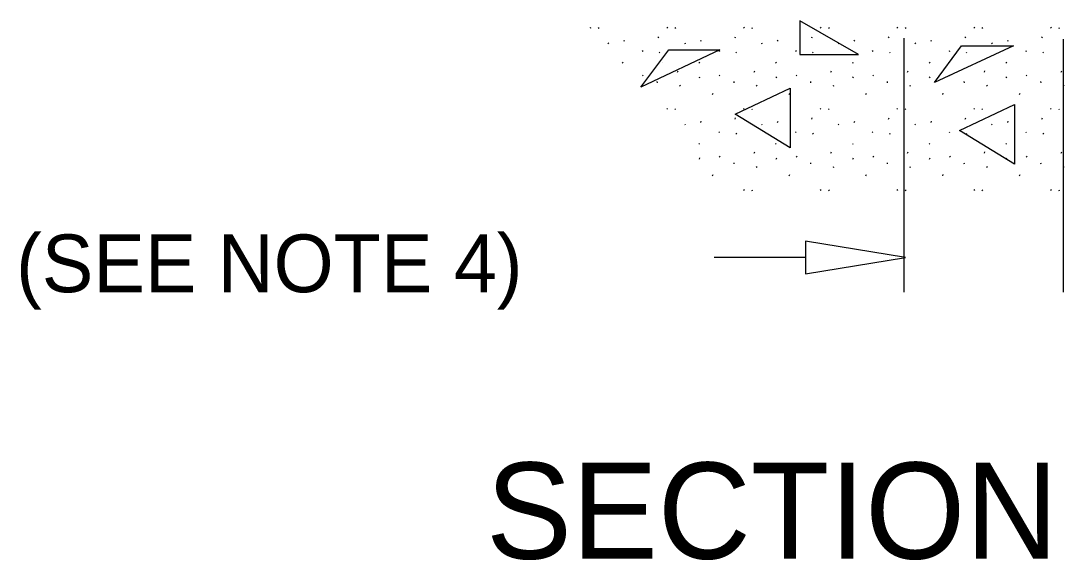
# Model space of a CAD drawing. Extents: x -1550.42 to -1543.2, y 2481.09 to 2491.
# Drawn here: x -1549.538 to -1548.454, y 2486.013 to 2486.573 of the extents above; entities that cross this region are included whole.
import ezdxf

# ---------------------------------------------------------------- set-up
doc = ezdxf.new("R2010")
doc.units = 0
for name, color, linetype in [('DETL-DIMS', 7, 'Continuous'), ('DETL-NOTE', 7, 'Continuous'), ('DETL-PATT', 7, 'Continuous'), ('DETL-TITL', 7, 'Continuous')]:
    doc.layers.add(name, color=color, linetype=linetype)

msp = doc.modelspace()

# ---------------------------------------------------------------- linework, layer by layer
at = {"layer": 'DETL-DIMS'}
for p, q in [((-1548.621, 2486.555), (-1548.621, 2486.291)), ((-1548.455, 2486.291), (-1548.455, 2486.554)), ((-1548.723, 2486.327), (-1548.818, 2486.327))]:
    msp.add_line(p, q, dxfattribs=at)
msp.add_lwpolyline([(-1548.723, 2486.344), (-1548.723, 2486.31), (-1548.619, 2486.327)], close=True, dxfattribs=at)
at = {"layer": 'DETL-PATT'}
for p, q in [((-1548.9468, 2486.5663), (-1548.9462, 2486.5654)), ((-1548.8671, 2486.5663), (-1548.8665, 2486.5654)), ((-1548.7874, 2486.5663), (-1548.7868, 2486.5654)), ((-1548.668, 2486.538), (-1548.729, 2486.573)), ((-1548.729, 2486.573), (-1548.729, 2486.538)), ((-1548.7077, 2486.5663), (-1548.7071, 2486.5654)), ((-1548.628, 2486.5663), (-1548.6274, 2486.5654)), ((-1548.5482, 2486.5663), (-1548.5476, 2486.5654)), ((-1548.4685, 2486.5663), (-1548.4679, 2486.5654)), ((-1548.9383, 2486.566), (-1548.9377, 2486.5651)), ((-1548.876, 2486.5552), (-1548.8754, 2486.5565)), ((-1548.8586, 2486.566), (-1548.858, 2486.5651)), ((-1548.7962, 2486.5552), (-1548.7956, 2486.5565)), ((-1548.7789, 2486.566), (-1548.7783, 2486.5651)), ((-1548.7165, 2486.5552), (-1548.7159, 2486.5565)), ((-1548.6991, 2486.566), (-1548.6985, 2486.5651)), ((-1548.6368, 2486.5552), (-1548.6362, 2486.5565)), ((-1548.6194, 2486.566), (-1548.6188, 2486.5651)), ((-1548.5571, 2486.5552), (-1548.5565, 2486.5565)), ((-1548.5397, 2486.566), (-1548.5391, 2486.5651)), ((-1548.4774, 2486.5552), (-1548.4768, 2486.5565)), ((-1548.46, 2486.566), (-1548.4594, 2486.5651)), ((-1548.9282, 2486.55), (-1548.9276, 2486.5491)), ((-1548.9115, 2486.5518), (-1548.9109, 2486.5531)), ((-1548.8485, 2486.55), (-1548.8479, 2486.5491)), ((-1548.8318, 2486.5518), (-1548.8312, 2486.5531)), ((-1548.7688, 2486.55), (-1548.7682, 2486.5491)), ((-1548.752, 2486.5518), (-1548.7514, 2486.5531)), ((-1548.6891, 2486.55), (-1548.6885, 2486.5491)), ((-1548.6723, 2486.5518), (-1548.6717, 2486.5531)), ((-1548.6094, 2486.55), (-1548.6088, 2486.5491)), ((-1548.5926, 2486.5518), (-1548.592, 2486.5531)), ((-1548.589, 2486.509), (-1548.561, 2486.547)), ((-1548.507, 2486.547), (-1548.589, 2486.509)), ((-1548.561, 2486.547), (-1548.507, 2486.547)), ((-1548.5297, 2486.55), (-1548.5291, 2486.5491)), ((-1548.5129, 2486.5518), (-1548.5123, 2486.5531)), ((-1548.894, 2486.504), (-1548.865, 2486.543)), ((-1548.812, 2486.543), (-1548.894, 2486.504)), ((-1548.8927, 2486.5422), (-1548.8921, 2486.5413)), ((-1548.875, 2486.5405), (-1548.8744, 2486.5396)), ((-1548.865, 2486.543), (-1548.812, 2486.543)), ((-1548.813, 2486.5422), (-1548.8124, 2486.5413)), ((-1548.7953, 2486.5405), (-1548.7947, 2486.5396)), ((-1548.7333, 2486.5422), (-1548.7327, 2486.5413)), ((-1548.729, 2486.538), (-1548.668, 2486.538)), ((-1548.7156, 2486.5405), (-1548.715, 2486.5396)), ((-1548.6536, 2486.5422), (-1548.653, 2486.5413)), ((-1548.6359, 2486.5405), (-1548.6353, 2486.5396)), ((-1548.5739, 2486.5422), (-1548.5733, 2486.5413)), ((-1548.5562, 2486.5405), (-1548.5556, 2486.5396)), ((-1548.4942, 2486.5422), (-1548.4936, 2486.5413)), ((-1548.4764, 2486.5405), (-1548.4758, 2486.5396)), ((-1548.9135, 2486.5299), (-1548.9129, 2486.529)), ((-1548.872, 2486.53), (-1548.872, 2486.53)), ((-1548.8337, 2486.5299), (-1548.8331, 2486.529)), ((-1548.754, 2486.5299), (-1548.7534, 2486.529)), ((-1548.6743, 2486.5299), (-1548.6737, 2486.529)), ((-1548.5946, 2486.5299), (-1548.594, 2486.529)), ((-1548.5149, 2486.5299), (-1548.5143, 2486.529)), ((-1548.8922, 2486.5166), (-1548.8916, 2486.5157)), ((-1548.856, 2486.5198), (-1548.8554, 2486.5212)), ((-1548.8332, 2486.5137), (-1548.8326, 2486.515)), ((-1548.8125, 2486.5166), (-1548.8119, 2486.5157)), ((-1548.7763, 2486.5198), (-1548.7757, 2486.5212)), ((-1548.7535, 2486.5137), (-1548.7529, 2486.515)), ((-1548.7327, 2486.5166), (-1548.7321, 2486.5157)), ((-1548.6966, 2486.5198), (-1548.696, 2486.5212)), ((-1548.6738, 2486.5137), (-1548.6732, 2486.515)), ((-1548.653, 2486.5166), (-1548.6524, 2486.5157)), ((-1548.6169, 2486.5198), (-1548.6163, 2486.5212)), ((-1548.5941, 2486.5137), (-1548.5935, 2486.515)), ((-1548.5733, 2486.5166), (-1548.5727, 2486.5157)), ((-1548.5372, 2486.5198), (-1548.5366, 2486.5212)), ((-1548.5144, 2486.5137), (-1548.5138, 2486.515)), ((-1548.4936, 2486.5166), (-1548.493, 2486.5157)), ((-1548.4574, 2486.5198), (-1548.4568, 2486.5212)), ((-1548.8773, 2486.5099), (-1548.8772, 2486.5086)), ((-1548.8538, 2486.506), (-1548.8532, 2486.5051)), ((-1548.7976, 2486.5099), (-1548.7975, 2486.5086)), ((-1548.796, 2486.476), (-1548.739, 2486.503)), ((-1548.7741, 2486.506), (-1548.7735, 2486.5051)), ((-1548.739, 2486.503), (-1548.739, 2486.441)), ((-1548.7179, 2486.5099), (-1548.7178, 2486.5086)), ((-1548.6944, 2486.506), (-1548.6938, 2486.5051)), ((-1548.6382, 2486.5099), (-1548.638, 2486.5086)), ((-1548.6147, 2486.506), (-1548.6141, 2486.5051)), ((-1548.5585, 2486.5099), (-1548.5583, 2486.5086)), ((-1548.535, 2486.506), (-1548.5344, 2486.5051)), ((-1548.4788, 2486.5099), (-1548.4786, 2486.5086)), ((-1548.4553, 2486.506), (-1548.4547, 2486.5051)), ((-1548.8196, 2486.4963), (-1548.819, 2486.4977)), ((-1548.7399, 2486.4963), (-1548.7393, 2486.4977)), ((-1548.6602, 2486.4963), (-1548.6596, 2486.4977)), ((-1548.5805, 2486.4963), (-1548.5799, 2486.4977)), ((-1548.5007, 2486.4963), (-1548.5001, 2486.4977)), ((-1548.8671, 2486.482), (-1548.8665, 2486.4811)), ((-1548.8586, 2486.4817), (-1548.858, 2486.4808)), ((-1548.7874, 2486.482), (-1548.7868, 2486.4811)), ((-1548.7789, 2486.4817), (-1548.7783, 2486.4808)), ((-1548.7077, 2486.482), (-1548.7071, 2486.4811)), ((-1548.6991, 2486.4817), (-1548.6985, 2486.4808)), ((-1548.628, 2486.482), (-1548.6274, 2486.4811)), ((-1548.6194, 2486.4817), (-1548.6188, 2486.4808)), ((-1548.563, 2486.459), (-1548.506, 2486.486)), ((-1548.5482, 2486.482), (-1548.5476, 2486.4811)), ((-1548.5397, 2486.4817), (-1548.5391, 2486.4808)), ((-1548.506, 2486.486), (-1548.506, 2486.424)), ((-1548.4685, 2486.482), (-1548.4679, 2486.4811)), ((-1548.46, 2486.4817), (-1548.4594, 2486.4808)), ((-1548.8318, 2486.4674), (-1548.8312, 2486.4688)), ((-1548.7962, 2486.4709), (-1548.7956, 2486.4722)), ((-1548.739, 2486.441), (-1548.796, 2486.476)), ((-1548.752, 2486.4674), (-1548.7514, 2486.4688)), ((-1548.7165, 2486.4709), (-1548.7159, 2486.4722)), ((-1548.6723, 2486.4674), (-1548.6717, 2486.4688)), ((-1548.6368, 2486.4709), (-1548.6362, 2486.4722)), ((-1548.5926, 2486.4674), (-1548.592, 2486.4688)), ((-1548.5571, 2486.4709), (-1548.5565, 2486.4722)), ((-1548.5129, 2486.4674), (-1548.5123, 2486.4688)), ((-1548.4774, 2486.4709), (-1548.4768, 2486.4722)), ((-1548.8485, 2486.4657), (-1548.8479, 2486.4648)), ((-1548.813, 2486.4578), (-1548.8124, 2486.4569)), ((-1548.7688, 2486.4657), (-1548.7682, 2486.4648)), ((-1548.7333, 2486.4578), (-1548.7327, 2486.4569)), ((-1548.6891, 2486.4657), (-1548.6885, 2486.4648)), ((-1548.6536, 2486.4578), (-1548.653, 2486.4569)), ((-1548.6094, 2486.4657), (-1548.6088, 2486.4648)), ((-1548.5739, 2486.4578), (-1548.5733, 2486.4569)), ((-1548.506, 2486.424), (-1548.563, 2486.459)), ((-1548.5297, 2486.4657), (-1548.5291, 2486.4648)), ((-1548.4942, 2486.4578), (-1548.4936, 2486.4569)), ((-1548.7953, 2486.4562), (-1548.7947, 2486.4553)), ((-1548.7156, 2486.4562), (-1548.715, 2486.4553)), ((-1548.6359, 2486.4562), (-1548.6353, 2486.4553)), ((-1548.5562, 2486.4562), (-1548.5556, 2486.4553)), ((-1548.4764, 2486.4562), (-1548.4758, 2486.4553)), ((-1548.8337, 2486.4456), (-1548.8331, 2486.4447)), ((-1548.7763, 2486.4355), (-1548.7757, 2486.4369)), ((-1548.754, 2486.4456), (-1548.7534, 2486.4447)), ((-1548.6966, 2486.4355), (-1548.696, 2486.4369)), ((-1548.6743, 2486.4456), (-1548.6737, 2486.4447)), ((-1548.6169, 2486.4355), (-1548.6163, 2486.4369)), ((-1548.5946, 2486.4456), (-1548.594, 2486.4447)), ((-1548.5372, 2486.4355), (-1548.5366, 2486.4369)), ((-1548.5149, 2486.4456), (-1548.5143, 2486.4447)), ((-1548.4574, 2486.4355), (-1548.4568, 2486.4369)), ((-1548.8332, 2486.4294), (-1548.8326, 2486.4307)), ((-1548.8125, 2486.4323), (-1548.8119, 2486.4314)), ((-1548.7976, 2486.4256), (-1548.7975, 2486.4243)), ((-1548.7535, 2486.4294), (-1548.7529, 2486.4307)), ((-1548.7327, 2486.4323), (-1548.7321, 2486.4314)), ((-1548.7179, 2486.4256), (-1548.7178, 2486.4243)), ((-1548.6738, 2486.4294), (-1548.6732, 2486.4307)), ((-1548.653, 2486.4323), (-1548.6524, 2486.4314)), ((-1548.6382, 2486.4256), (-1548.638, 2486.4243)), ((-1548.5941, 2486.4294), (-1548.5935, 2486.4307)), ((-1548.5733, 2486.4323), (-1548.5727, 2486.4314)), ((-1548.5585, 2486.4256), (-1548.5583, 2486.4243)), ((-1548.5144, 2486.4294), (-1548.5138, 2486.4307)), ((-1548.4936, 2486.4323), (-1548.493, 2486.4314)), ((-1548.4788, 2486.4256), (-1548.4786, 2486.4243)), ((-1548.7741, 2486.4216), (-1548.7735, 2486.4207)), ((-1548.6944, 2486.4216), (-1548.6938, 2486.4207)), ((-1548.6147, 2486.4216), (-1548.6141, 2486.4207)), ((-1548.535, 2486.4216), (-1548.5344, 2486.4207)), ((-1548.4553, 2486.4216), (-1548.4547, 2486.4207)), ((-1548.8196, 2486.412), (-1548.819, 2486.4133)), ((-1548.7399, 2486.412), (-1548.7393, 2486.4133)), ((-1548.6602, 2486.412), (-1548.6596, 2486.4133)), ((-1548.5805, 2486.412), (-1548.5799, 2486.4133)), ((-1548.5007, 2486.412), (-1548.5001, 2486.4133)), ((-1548.7874, 2486.3977), (-1548.7868, 2486.3968)), ((-1548.7789, 2486.3973), (-1548.7783, 2486.3964)), ((-1548.7077, 2486.3977), (-1548.7071, 2486.3968)), ((-1548.6991, 2486.3973), (-1548.6985, 2486.3964)), ((-1548.628, 2486.3977), (-1548.6274, 2486.3968)), ((-1548.6194, 2486.3973), (-1548.6188, 2486.3964)), ((-1548.5482, 2486.3977), (-1548.5476, 2486.3968)), ((-1548.5397, 2486.3973), (-1548.5391, 2486.3964)), ((-1548.4685, 2486.3977), (-1548.4679, 2486.3968)), ((-1548.46, 2486.3973), (-1548.4594, 2486.3964))]:
    msp.add_line(p, q, dxfattribs=at)

# ---------------------------------------------------------------- texts
at = {"layer": 'DETL-NOTE'}
msp.add_text('(SEE NOTE 4)', height=0.06, dxfattribs=at).set_placement((-1549.543, 2486.291))
at = {"layer": 'DETL-TITL'}
msp.add_text('SECTION A-A', height=0.100002, dxfattribs=at).set_placement((-1549.0548, 2486.014))

doc.saveas('drawing.dxf')
